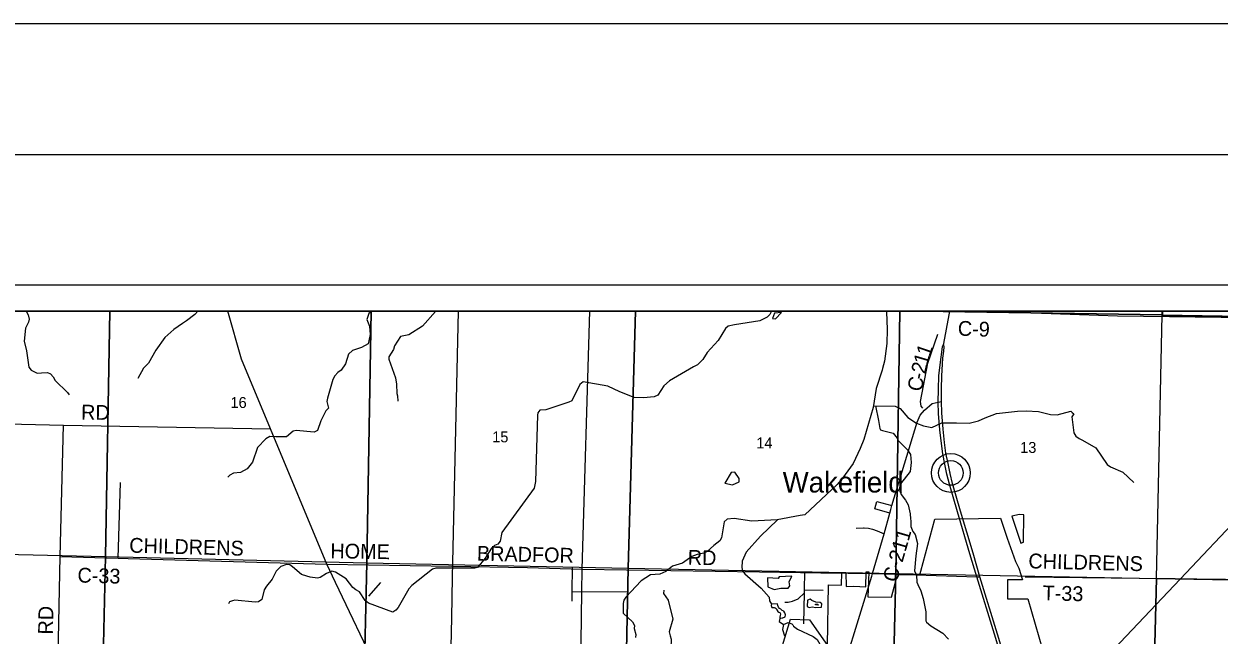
# Model space of a CAD drawing. Extents: x 0 to 68.9, y -26.1 to 22.
# Drawn here: x 2.979 to 7.562, y 19.658 to 22 of the extents above; entities that cross this region are included whole.
import ezdxf

# ---------------------------------------------------------------- set-up
doc = ezdxf.new("R2010")
doc.units = 0
for name, color, linetype in [('GM_X_Corporation', 7, 'Continuous'), ('GM_X_County_Road', 7, 'Continuous'), ('GM_X_County_Road_Text', 7, 'Continuous'), ('GM_X_Minor_Lake', 7, 'Continuous'), ('GM_X_Minor_River', 7, 'Continuous'), ('GM_X_Rail_Line', 7, 'Continuous'), ('GM_X_Section_Text', 7, 'Continuous'), ('GM_X_State_Route', 7, 'Continuous'), ('GM_X_Township_Road', 7, 'Continuous'), ('GM_X_Township_Road_Text', 7, 'Continuous'), ('GM_X_Unincorporated', 7, 'Continuous'), ('GM_X_Unincorporated_Location', 7, 'Continuous'), ('GM_X_Unincorporated_Text', 7, 'Continuous'), ('GM_X_US_Route', 7, 'Continuous'), ('SH_Border', 7, 'Continuous'), ('SH_Cut_Line', 7, 'Continuous'), ('SH_Data', 7, 'Continuous')]:
    doc.layers.add(name, color=color, linetype=linetype)

msp = doc.modelspace()

# ---------------------------------------------------------------- linework, layer by layer
at = {"layer": 'GM_X_Corporation'}
for points in [[(7.3445, 20.9), (2.1, 20.9), (2.1, 14.9646), (3.342, 14.9339), (4.4236, 14.9071), (5.6162, 14.8776), (5.6466, 14.8768), (5.7051, 14.8754), (5.7249, 14.8749), (5.8078, 14.8728), (5.8237, 14.8724), (6.3807, 14.8544), (6.5963, 14.8495), (6.6831, 14.8475), (7.2088, 14.8355), (7.7563, 14.8264), (8.2579, 14.8244), (8.6486, 14.8265), (8.7556, 14.8254), (8.9, 14.8227), (8.9, 20.8594), (8.5115, 20.8629), (7.8412, 20.8763), (7.3443, 20.8819)], [(3.3089, 20.9), (2.3112, 20.9), (2.292, 19.9828), (3.2917, 19.9594)], [(4.3112, 20.9), (3.3089, 20.9), (3.2917, 19.9594), (4.2937, 19.9358)], [(5.3236, 20.9), (4.3112, 20.9), (4.2937, 19.9358), (5.2957, 19.9154)], [(6.3372, 20.9), (5.3236, 20.9), (5.2957, 19.9154), (6.3218, 19.8939)], [(6.4195, 20.9), (6.3372, 20.9), (6.3218, 19.8939), (7.3211, 19.8752), (7.3434, 20.8855)], [(7.3437, 20.9), (6.4195, 20.9), (7.3434, 20.8855)], [(8.3424, 20.9), (7.3437, 20.9), (7.3434, 20.8855), (8.3421, 20.8691)], [(8.9, 20.8594), (8.9, 20.9), (7.3445, 20.9), (7.3443, 20.8819), (7.8412, 20.8763), (8.5115, 20.8629)], [(7.3434, 20.8855), (8.3421, 20.8691), (8.3254, 19.8572), (7.3211, 19.8752)], [(2.292, 19.9828), (3.2917, 19.9594), (3.2698, 18.9483), (2.2709, 18.9749)], [(3.2917, 19.9594), (4.2937, 19.9358), (4.2714, 18.9289), (3.2698, 18.9483)], [(4.2937, 19.9358), (5.2957, 19.9154), (5.2753, 18.9061), (4.2714, 18.9289)], [(6.3218, 19.8939), (6.2983, 18.8857), (5.2753, 18.9061), (5.2957, 19.9154)], [(6.3218, 19.8939), (7.3211, 19.8752), (7.2954, 18.8682), (6.2983, 18.8857)], [(8.3254, 19.8572), (8.2978, 18.8494), (7.2954, 18.8682), (7.3211, 19.8752)]]:
    msp.add_lwpolyline(points, close=True, dxfattribs=at)
msp.add_lwpolyline([(5.8873, 19.6186), (5.9181, 19.7194), (5.9913, 19.7169), (6.0597, 19.6181), (6.0645, 19.8504), (6.1136, 19.8497), (6.1156, 19.8981), (6.1305, 19.8981), (6.1315, 19.8452), (6.1617, 19.8454), (6.2077, 19.8435), (6.2081, 19.9008), (6.2184, 19.9006), (6.2163, 19.8344), (6.2154, 19.8049), (6.3058, 19.8039), (6.3205, 19.8612), (6.3211, 19.8902), (6.4137, 19.8892), (6.4179, 19.9033), (6.4712, 20.102), (6.724, 20.1065), (6.749, 20.0297), (6.7814, 19.9407), (6.7937, 19.9153), (6.8073, 19.8701), (6.7505, 19.8701), (6.7505, 19.7974), (6.8284, 19.7974), (6.885, 19.6036)], dxfattribs=at)
at = {"layer": 'GM_X_County_Road'}
for p, q in [((3.3412, 19.953), (3.3493, 20.2426)), ((3.3792, 19.9519), (4.1406, 19.9306)), ((4.1406, 19.9306), (4.6202, 19.9225)), ((5.1202, 19.9114), (5.7998, 19.9014)), ((5.7998, 19.9014), (6.0353, 19.8973)), ((6.0353, 19.8973), (6.0454, 19.8971)), ((6.0454, 19.8971), (6.2326, 19.8938)), ((6.2326, 19.8938), (6.2427, 19.8938)), ((6.2427, 19.8938), (6.633, 19.882)), ((6.633, 19.882), (6.6445, 19.8817))]:
    msp.add_line(p, q, dxfattribs=at)
for points in [[(6.6627, 20.9), (7.1715, 20.8813), (7.6685, 20.8758)], [(6.4257, 20.5278), (6.4189, 20.5352), (6.4168, 20.5531), (6.4444, 20.7001), (6.4828, 20.8113)], [(6.2297, 19.8842), (6.2326, 19.8938), (6.2772, 20.0465), (6.299, 20.1259), (6.3028, 20.1398), (6.3069, 20.1548), (6.4036, 20.4738), (6.4158, 20.5005), (6.4321, 20.5207), (6.4614, 20.5456), (6.4847, 20.551), (6.4968, 20.5538)], [(2.3761, 20.4805), (3.131, 20.4632), (3.9247, 20.4486)], [(3.0894, 18.8685), (3.0937, 18.8759), (3.0977, 18.9468), (3.1188, 19.9596), (3.131, 20.4632)], [(6.299, 20.1259), (6.2412, 20.1417), (6.2491, 20.1706), (6.3069, 20.1548)], [(6.17, 20.0681), (6.1987, 20.069), (6.2006, 20.0688)], [(6.2006, 20.0688), (6.218, 20.0677), (6.2332, 20.0647), (6.2505, 20.0578), (6.2772, 20.0465)], [(3.1188, 19.9596), (3.3412, 19.953), (3.3792, 19.9519)], [(4.6202, 19.9225), (4.9099, 19.9176), (5.1202, 19.9114)], [(5.9979, 19.1418), (6.0812, 19.3992), (6.2297, 19.8842)]]:
    msp.add_lwpolyline(points, dxfattribs=at)
at = {"layer": 'GM_X_Minor_Lake'}
for points in [[(5.8493, 20.8713), (5.861, 20.8696), (5.8834, 20.8939)], [(5.8834, 20.8939), (5.8572, 20.8914), (5.8493, 20.8713)], [(5.7216, 20.2582), (5.7047, 20.2822), (5.691, 20.2817), (5.6663, 20.2406)], [(5.6663, 20.2406), (5.6958, 20.2343), (5.7214, 20.246), (5.7216, 20.2582)], [(6.8123, 20.1198), (6.796, 20.1209), (6.7674, 20.1135), (6.8014, 20.0103)], [(6.8014, 20.0103), (6.8113, 20.0139), (6.8123, 20.1198)], [(5.923, 19.8842), (5.8752, 19.8821), (5.8713, 19.8753), (5.8308, 19.878), (5.8312, 19.8429)], [(5.8312, 19.8429), (5.8557, 19.8337), (5.8808, 19.8385), (5.91, 19.8383), (5.9162, 19.8474), (5.9135, 19.8623), (5.923, 19.8842)], [(6.0376, 19.7653), (6.039, 19.7786), (6.0319, 19.7834), (6.0152, 19.7845), (5.9998, 19.7905), (5.9938, 19.796), (5.9835, 19.7916)], [(5.8451, 19.7774), (5.8447, 19.7719), (5.8456, 19.7682), (5.847, 19.7636), (5.8511, 19.7636), (5.8558, 19.7636), (5.8599, 19.7627), (5.8636, 19.7599), (5.8664, 19.7553), (5.8696, 19.7493), (5.8733, 19.7466), (5.8784, 19.7443), (5.8798, 19.7388), (5.8788, 19.7332), (5.8775, 19.7268), (5.877, 19.7217), (5.8816, 19.7231), (5.8858, 19.7245), (5.889, 19.7249), (5.8974, 19.728)], [(5.8974, 19.728), (5.8987, 19.736), (5.8964, 19.7438), (5.8922, 19.7498), (5.8867, 19.753), (5.8816, 19.7572), (5.8765, 19.7609), (5.8728, 19.7659), (5.8701, 19.7719), (5.8687, 19.7779), (5.8451, 19.7774)], [(5.9835, 19.7916), (5.9826, 19.768), (5.9905, 19.764), (6.0012, 19.7672), (6.0156, 19.7639), (6.0376, 19.7653)], [(6.0139, 19.7738), (6.0139, 19.7765), (6.0238, 19.7763)], [(6.0238, 19.7763), (6.0241, 19.7725), (6.0139, 19.7738)]]:
    msp.add_lwpolyline(points, dxfattribs=at)
at = {"layer": 'GM_X_Minor_River'}
for points in [[(2.9883, 20.9), (2.9952, 20.8856), (2.9991, 20.8692), (2.9977, 20.8574), (2.9859, 20.8344), (2.9804, 20.7842), (2.9892, 20.7471), (2.9982, 20.6853), (3.0078, 20.6729), (3.0304, 20.6621), (3.0471, 20.6626), (3.0702, 20.6648), (3.0811, 20.6589), (3.0922, 20.6476), (3.0999, 20.6337), (3.1472, 20.5882), (3.1535, 20.5786)], [(3.6466, 20.9), (3.6346, 20.8862), (3.6023, 20.8625), (3.5877, 20.8525), (3.5543, 20.8291), (3.5203, 20.7981), (3.4853, 20.7501), (3.4571, 20.7003), (3.4374, 20.6813), (3.4165, 20.6409)], [(4.3142, 20.9), (4.3013, 20.8908), (4.2937, 20.8673), (4.305, 20.8423), (4.307, 20.8095), (4.2999, 20.7746), (4.2742, 20.7602), (4.2387, 20.7483), (4.2241, 20.7341), (4.2128, 20.6974), (4.1956, 20.6737), (4.1826, 20.6648), (4.1717, 20.652), (4.1639, 20.6373), (4.1432, 20.5657), (4.1414, 20.5532), (4.147, 20.5275), (4.1366, 20.5178), (4.1184, 20.4789), (4.1052, 20.4426), (4.0926, 20.4356), (4.0233, 20.4418), (4.0115, 20.4402), (3.9861, 20.4186), (3.9607, 20.4179), (3.9459, 20.4178), (3.9217, 20.4198), (3.9075, 20.4109), (3.875, 20.3768), (3.8554, 20.3212), (3.8359, 20.2949), (3.8095, 20.2809), (3.7826, 20.2792), (3.7692, 20.2714), (3.7618, 20.2632)], [(5.846, 20.9), (5.8393, 20.8868), (5.8285, 20.8759), (5.8002, 20.8624), (5.7036, 20.8471), (5.68, 20.8418), (5.6689, 20.8337), (5.6411, 20.7877), (5.5993, 20.7413), (5.5821, 20.7145), (5.562, 20.6936), (5.5471, 20.6859), (5.4551, 20.632), (5.4324, 20.6137), (5.4101, 20.5776), (5.3963, 20.5717), (5.3553, 20.5672), (5.3193, 20.5683), (5.2636, 20.5899), (5.2182, 20.6125), (5.1234, 20.6285), (5.1103, 20.6184), (5.0803, 20.5561), (5.0692, 20.5502), (4.9807, 20.5214), (4.9568, 20.52), (4.9491, 20.5102), (4.9485, 20.5007), (4.9414, 20.2466), (4.9363, 20.2208), (4.8111, 20.0517), (4.8055, 20.0179), (4.7958, 20.0062), (4.7836, 20.0023), (4.772, 19.9911), (4.7482, 19.9526), (4.7183, 19.9178), (4.7084, 19.9149), (4.5583, 19.9144), (4.5454, 19.9108), (4.4669, 19.8483), (4.4553, 19.8359), (4.4137, 19.7647), (4.4059, 19.7534), (4.3933, 19.7468), (4.3011, 19.7802), (4.2876, 19.7904), (4.2655, 19.8239), (4.2524, 19.8314), (4.2408, 19.8408), (4.2149, 19.8737), (4.1741, 19.8993), (4.1601, 19.9033), (4.1391, 19.895), (4.1149, 19.8787), (4.1047, 19.877), (4.0771, 19.8805), (4.0639, 19.8846), (4.0435, 19.89), (4.0096, 19.9203), (3.9991, 19.9274), (3.9867, 19.9295), (3.9649, 19.9216), (3.946, 19.9033), (3.9318, 19.8723), (3.9097, 19.8464), (3.901, 19.8313), (3.8912, 19.7949), (3.8793, 19.786), (3.866, 19.7847), (3.7881, 19.792), (3.7786, 19.7891), (3.7671, 19.7863), (3.7632, 19.7787)], [(4.5586, 20.9), (4.5577, 20.8988), (4.5073, 20.8415), (4.4552, 20.8086), (4.4236, 20.8023), (4.4006, 20.7669), (4.3961, 20.7522), (4.3789, 20.7251), (4.378, 20.7152), (4.4035, 20.6442), (4.4084, 20.6197), (4.4096, 20.5846), (4.4121, 20.575), (4.4132, 20.5541)], [(6.2871, 20.9), (6.2867, 20.8975), (6.2889, 20.8291), (6.2874, 20.7761), (6.2783, 20.7084), (6.2714, 20.6801), (6.2701, 20.673), (6.2471, 20.6034), (6.2348, 20.5302), (6.1993, 20.4075), (6.185, 20.3733), (6.1583, 20.3156), (6.1175, 20.2602), (6.097, 20.2354), (5.9735, 20.1193), (5.9558, 20.1166)], [(6.236, 20.5373), (6.3197, 20.5356), (6.3385, 20.5271), (6.3688, 20.4918), (6.4017, 20.4704), (6.4288, 20.4598), (6.4603, 20.4544), (6.4988, 20.4716), (6.5545, 20.4719), (6.6036, 20.4698), (6.6389, 20.4795), (6.6651, 20.4906), (6.7075, 20.5076), (6.7881, 20.5168), (6.8213, 20.5182), (6.8692, 20.5153), (6.9055, 20.5056), (6.9146, 20.5042), (6.9405, 20.502), (6.9934, 20.5161), (6.9986, 20.5114), (7.0046, 20.5059), (6.9966, 20.4948), (7.004, 20.4331), (7.0117, 20.4212), (7.0252, 20.4121), (7.0378, 20.4047)], [(6.2439, 20.5371), (6.2561, 20.4801), (6.2614, 20.4503), (6.2639, 20.4453), (6.2715, 20.4421), (6.3115, 20.4315), (6.327, 20.4125), (6.328, 20.4064), (6.3665, 20.3678), (6.379, 20.35), (6.3815, 20.3203), (6.3771, 20.2852), (6.3396, 20.2373), (6.3359, 20.2157), (6.3426, 20.1966), (6.3599, 20.1753), (6.3693, 20.1575), (6.3775, 20.1236), (6.3785, 20.1038), (6.3794, 20.0958), (6.3803, 20.0745), (6.3874, 20.0558), (6.3958, 20.0438), (6.4048, 20.0098), (6.3993, 19.9625), (6.3942, 19.9042), (6.4014, 19.8877), (6.4029, 19.8607), (6.4061, 19.8523), (6.4179, 19.8277), (6.4274, 19.7982), (6.437, 19.7471), (6.4368, 19.7126), (6.4397, 19.7076), (6.4564, 19.6935), (6.5018, 19.6657), (6.5244, 19.6431)], [(7.0378, 20.4047), (7.0894, 20.3753), (7.133, 20.3123), (7.1446, 20.3033), (7.192, 20.2829), (7.2349, 20.2428)], [(5.9558, 20.1166), (5.8676, 20.1003), (5.7697, 20.0945), (5.702, 20.1046), (5.6751, 20.1029), (5.6639, 20.092), (5.6544, 20.0312), (5.6481, 20.0199), (5.6243, 20.0013), (5.5992, 19.9789), (5.5866, 19.9723), (5.5611, 19.9678), (5.5405, 19.9598), (5.5047, 19.9346), (5.4659, 19.9224), (5.4408, 19.9019), (5.4286, 19.8964), (5.4179, 19.8921), (5.3811, 19.8897), (5.3454, 19.866), (5.2873, 19.8031), (5.2792, 19.7918), (5.277, 19.7789), (5.2771, 19.7423), (5.3132, 19.7096), (5.3198, 19.6957), (5.3192, 19.6839), (5.3256, 19.6602), (5.3246, 19.6488)], [(5.868, 20.1004), (5.8035, 20.0375), (5.7485, 19.976), (5.7334, 19.942), (5.7322, 19.9169), (5.735, 19.9042), (5.7439, 19.893), (5.8054, 19.8381), (5.8362, 19.8032), (5.8382, 19.7894), (5.8451, 19.7775)], [(5.4326, 19.8304), (5.4309, 19.8179), (5.449, 19.7924), (5.4677, 19.7192), (5.4531, 19.6707), (5.457, 19.6554), (5.4613, 19.6427), (5.4614, 19.6282), (5.4545, 19.602), (5.4576, 19.5665), (5.4361, 19.4926), (5.4238, 19.4635), (5.4212, 19.4502), (5.4355, 19.4023), (5.434, 19.3611)], [(5.877, 19.7217), (5.8753, 19.7109), (5.891, 19.6988), (5.909, 19.7061), (5.9229, 19.7012), (5.9272, 19.6983), (5.93, 19.6922), (5.9457, 19.6814)], [(5.891, 19.6988), (5.8874, 19.6799), (5.8958, 19.656)], [(5.9457, 19.6814), (6.0053, 19.6527), (6.0203, 19.6417), (6.0361, 19.6151), (6.0373, 19.577), (6.045, 19.5635), (6.0547, 19.5549), (6.0789, 19.5334), (6.1239, 19.4833), (6.1727, 19.4385), (6.1893, 19.4111), (6.1891, 19.4012), (6.1795, 19.3755), (6.1654, 19.354), (6.1637, 19.3415), (6.1705, 19.32), (6.1844, 19.2964)]]:
    msp.add_lwpolyline(points, dxfattribs=at)
at = {"layer": 'GM_X_Rail_Line'}
msp.add_lwpolyline([(4.6151, 19.5012), (4.6195, 19.7243), (4.6224, 19.8801), (4.645, 20.9)], dxfattribs=at)
at = {"layer": 'GM_X_State_Route'}
msp.add_line((5.1202, 19.9114), (5.1496, 20.9), dxfattribs=at)
for points in [[(4.5998, 18.9522), (4.4985, 19.1804), (4.1746, 19.8594), (4.1406, 19.9306), (3.9247, 20.4486), (3.8136, 20.7161), (3.7609, 20.9)], [(6.9854, 19.4221), (6.995, 19.4321), (7.136, 19.581), (7.4128, 19.8732), (7.6543, 20.1282), (8.3388, 20.8623)], [(5.1114, 19.3396), (5.1189, 19.8245), (5.1202, 19.9114)]]:
    msp.add_lwpolyline(points, dxfattribs=at)
at = {"layer": 'GM_X_Township_Road'}
for p, q in [((5.0818, 19.8256), (5.0829, 19.9176)), ((4.3015, 19.8076), (4.3476, 19.8594)), ((6.8174, 19.8817), (7.5858, 19.8732)), ((5.0814, 19.7889), (5.0818, 19.8256)), ((5.0818, 19.8256), (5.2919, 19.8245)), ((5.9718, 19.8317), (6.0437, 19.8308))]:
    msp.add_line(p, q, dxfattribs=at)
for points in [[(5.9698, 19.7016), (5.9716, 19.8199), (5.9718, 19.8317), (5.9728, 19.9014)], [(5.8961, 19.7842), (5.909, 19.7849), (5.9263, 19.7884), (5.9479, 19.7968), (5.9716, 19.8199)]]:
    msp.add_lwpolyline(points, dxfattribs=at)
at = {"layer": 'GM_X_Unincorporated'}
for radius in [0.0744, 0.0472]:
    msp.add_circle((6.5332, 20.2797), radius, dxfattribs=at)
at = {"layer": 'GM_X_Unincorporated_Location'}
msp.add_line((6.5332, 20.2797), (6.5332, 20.2797), dxfattribs=at)
at = {"layer": 'GM_X_US_Route'}
msp.add_line((6.5263, 20.8858), (6.529, 20.9), dxfattribs=at)
for points in [[(6.5054, 20.7715), (6.5056, 20.775), (6.5263, 20.8858)], [(6.7282, 19.5691), (6.7005, 19.6622), (6.633, 19.882), (6.606, 19.97), (6.5583, 20.1303), (6.5275, 20.2366), (6.5182, 20.2746), (6.5101, 20.3129), (6.5024, 20.3529), (6.4968, 20.3929), (6.4911, 20.4442), (6.4864, 20.5068), (6.4847, 20.551), (6.4859, 20.6001), (6.4874, 20.6521), (6.4949, 20.7143), (6.4987, 20.7428), (6.5008, 20.7641), (6.5054, 20.7715)], [(6.4976, 20.5934), (6.4977, 20.6013), (6.4989, 20.6518), (6.5026, 20.7197), (6.5058, 20.7461), (6.5077, 20.7634), (6.5054, 20.7715)], [(6.7397, 19.5688), (6.7119, 19.6618), (6.6445, 19.8817), (6.6181, 19.9728), (6.5704, 20.1331), (6.5396, 20.2394), (6.5303, 20.2774), (6.5222, 20.3157), (6.5144, 20.3557), (6.5089, 20.3957), (6.5032, 20.4469), (6.4984, 20.5096), (6.4968, 20.5538), (6.4976, 20.5934)]]:
    msp.add_lwpolyline(points, dxfattribs=at)
at = {"layer": 'SH_Border'}
msp.add_lwpolyline([(1.5, 21.5), (33.5, 21.5), (33.5, 0.5), (1.5, 0.5)], close=True, dxfattribs=at)
at = {"layer": 'SH_Cut_Line'}
msp.add_lwpolyline([(0, 0), (34, 0), (34, 22), (0, 22)], close=True, dxfattribs=at)
at = {"layer": 'SH_Data'}
for p, q in [((1.827, 21), (8.827, 21)), ((1.927, 20.9), (8.727, 20.9))]:
    msp.add_line(p, q, dxfattribs=at)

# ---------------------------------------------------------------- texts
at = {"layer": 'GM_X_County_Road_Text'}
for s, height, rotation, p in [('C-9', 0.05682, 357.7089, (6.559, 20.806)), ('1', 0.0568, 71.1895, (6.4521, 20.7218)), ('1', 0.0568, 73.5992, (6.4425, 20.6891)), ('2', 0.0568, 77.3119, (6.4351, 20.6562)), ('C', 0.0568, 77.9477, (6.4206, 20.5884)), ('-', 0.0568, 77.9477, (6.4303, 20.6337)), ('RD', 0.05682, 359.0128, (3.1983, 20.4845)), ('CHILDRENS', 0.05682, 358.4088, (3.3827, 19.9745)), ('C-211', 0.05682, 73.9039, (6.3253, 19.8573)), ('HOME', 0.05682, 359.0652, (4.1541, 19.9529)), ('BRADFOR', 0.05682, 358.6909, (4.7157, 19.9437)), ('RD', 0.05682, 359.0128, (5.5241, 19.9278)), ('C-33', 0.05682, 358.2847, (3.1841, 19.8602)), ('RD', 0.05682, 89.0123, (3.0906, 19.6601))]:
    msp.add_text(s, height=height, rotation=rotation, dxfattribs=at).set_placement(p)
at = {"layer": 'GM_X_Section_Text'}
for s, p in [('16', (3.7713, 20.5285)), ('15', (4.7747, 20.3969)), ('14', (5.7872, 20.3738)), ('13', (6.7988, 20.3564))]:
    msp.add_text(s, height=0.04186, rotation=0, dxfattribs=at).set_placement(p)
at = {"layer": 'GM_X_Township_Road_Text'}
for s, rotation, p in [('CHILDRENS', 358.5311, (6.8298, 19.9145)), ('T-33', 358.5864, (6.8843, 19.7919))]:
    msp.add_text(s, height=0.05682, rotation=rotation, dxfattribs=at).set_placement(p)
at = {"layer": 'GM_X_Unincorporated_Text'}
msp.add_text('Wakefield', height=0.07898, rotation=0, dxfattribs=at).set_placement((5.8884, 20.2046))

doc.saveas('drawing.dxf')
